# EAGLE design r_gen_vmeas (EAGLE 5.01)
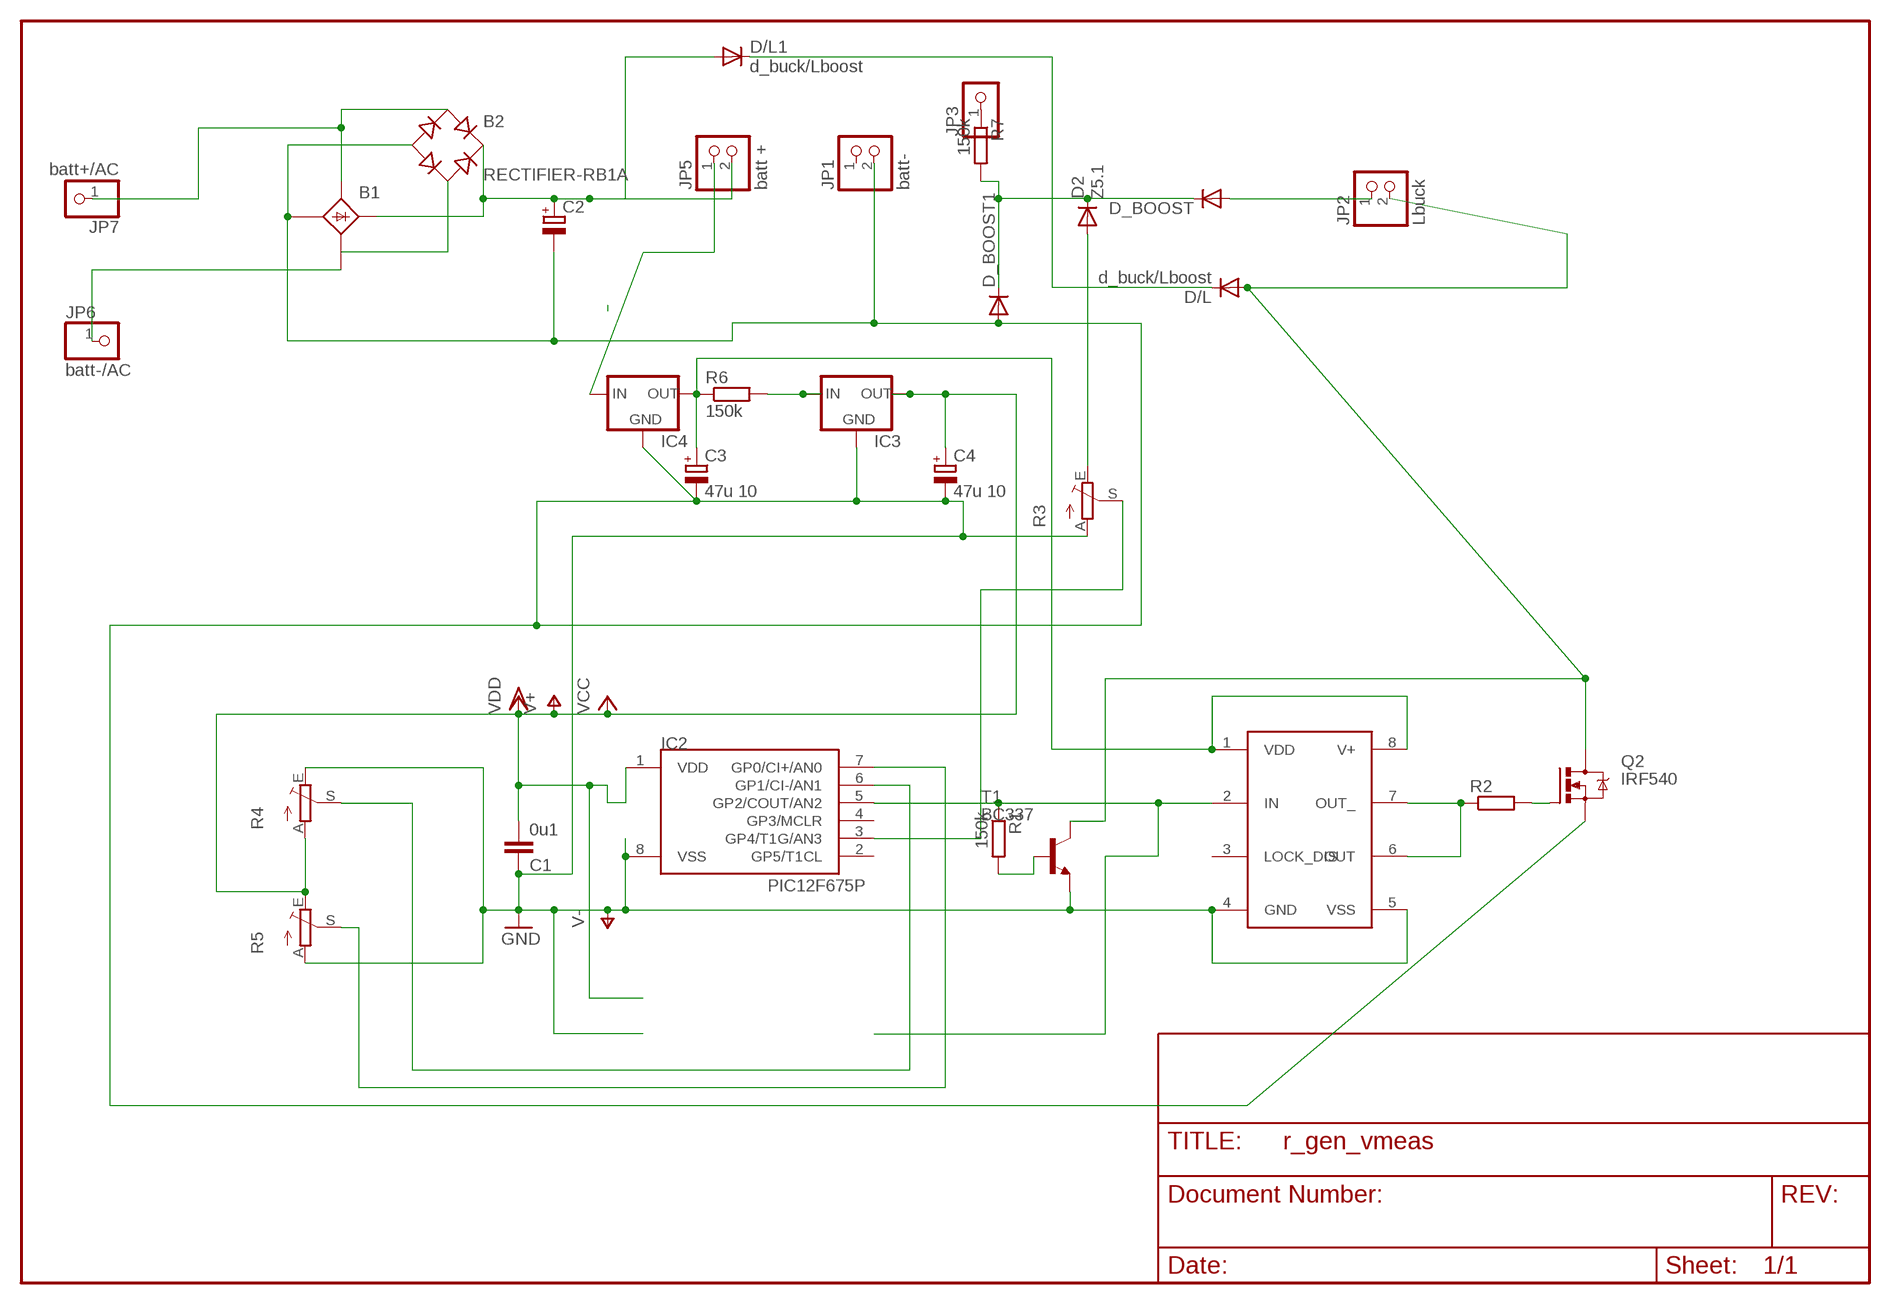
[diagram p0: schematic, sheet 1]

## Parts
B1  B25A-  [B25A-]
B2  RECTIFIER-RB1A  [RB1A]
C1  0u1  C-EU050-025X075  [C050-025X075]
C2  CPOL-EUE7.5-18  [E7,5-18]
C3  47u 10  CPOL-EUE2,5-6E  [E2,5-6E]
C4  47u 10  CPOL-EUE2.5-6  [E2,5-6]
D2  Z5.1  DIODE-D-7.5  [D-7.5]
D/L  d_buck/Lboost  DIODE-C1702-05  [C1702-05]
D/L1  d_buck/Lboost  DIODE-DO201-15  [DO201-15]
D_BOOST  DIODE-DO201-15  [DO201-15]
D_BOOST1  DIODE-DO201-15  [DO201-15]
IC1  TC4432X  [SO-08]
IC2  PIC12F675P  [DIL8]
IC3  78LXX  [78LXX]
IC4  78LXX  [78LXX]
JP1  batt-  PINHD-1X2  [1X02]
JP2  Lbuck  PINHD-1X2  [1X02]
JP3  PINHD-1X1  [1X01]
JP5  batt +  PINHD-1X2  [1X02]
JP6  batt-/AC  PINHD-1X1  [1X01]
JP7  batt+/AC  PINHD-1X1  [1X01]
Q2  IRF540  [TO220BV]
R1  150k  R-EU_0207/12  [0207/12]
R2  R-EU_R1206  [R1206]
R3  TRIM_EU-CA6V  [CA6V]
R4  TRIM_EU-CA6V  [CA6V]
R5  TRIM_EU-CA6V  [CA6V]
R6  150k  R-EU_0204/7  [0204/7]
R7  150k  R-EU_0207/12  [0207/12]
T1  BC337  [TO92]

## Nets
LOAD: D2.C D_BOOST1.C D_BOOST.C R7.2
N$1: IC4.IN JP5.1
N$2: D/L1.C D/L.C
N$3: B1.AC2-(AC2) JP6.1
N$4: C3.+ IC1.1(VDD) IC1.8(V+) IC4.OUT R6.1
N$5: D_BOOST.A JP2.1
N$6: R1.2 T1.2(B)
N$7: IC1.6(OUT) IC1.7(OUT_) R2.1
N$8: B1.AC1 B2.AC1 JP7.1
N$9: D/L.A JP2.2 Q2.D T1.3(C)
N$10: B1.+ B2.+ C2.+ D/L1.A JP5.2
N$11: B1.AC2 B2.AC2
N$12: IC2.3(GP4/T1G/AN3) R3.S
N$13: IC2.7(GP0/CI+/AN0) R5.S
N$14: IC1.2(IN) IC2.5(GP2/COUT/AN2) R1.1
N$15: IC2.6(GP1/CI-/AN1) R4.S
N$16: D2.A R3.E
N$17: Q2.G R2.2
N$19: JP3.1 R7.1
N$20: IC3.IN R6.2
V+: C1.2 C4.+ IC2.1(VDD) IC3.OUT R4.A R5.E ; supply symbol labelled VCC, VDD
V-: B1.-1(-) B2.- C1.1 C2.- C3.- C4.- D_BOOST1.A IC1.4(GND) IC1.5(VSS) IC2.8(VSS) IC3.GND IC4.GND JP1.2 Q2.S R3.A R4.E R5.A T1.1(E) ; supply symbol labelled GND
Unconnected: B1.+1(+) B1.- B1.AC1-(AC1) IC1.3(LOCK_DIS) IC2.2(GP5/T1CL) IC2.4(GP3/MCLR) JP1.1

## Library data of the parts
B1 = rectifier:B25A-: RECTIFIER 25-A bridge
B2 = rectifier:RECTIFIER-: Rectifier
C1 = rcl:C-EU: CAPACITOR, European symbol
C2-C4 = rcl:CPOL-EU: POLARIZED CAPACITOR, European symbol
D2 D/L D/L1 D_BOOST D_BOOST1 = diode:DIODE-: DIODE
IC1 = microchip:TC4432
IC2 = microchip-3:PIC12F6*: uPC nW 1k Program Flash memory 2x Timer Comparator 10b A/D converter/ 4xIN
IC3 IC4 = v-reg:78LXX: VOLTAGE REGULATOR
JP1 JP2 JP5 = pinhead:PINHD-1X2: PIN HEADER
JP3 JP6 JP7 = pinhead:PINHD-1X1: PIN HEADER
Q2 = transistor-power:IRF540: HEXFET Power MOSFET
R1 R6 R7 = rcl:R-EU_: RESISTOR, European symbol
R2 = rcl-2:R-EU_: RESISTOR, European symbol
R3-R5 = pot:TRIM_EU-: POTENTIOMETER
T1 = transistor-neu-to92:BC337: NPN TRANSISTOR

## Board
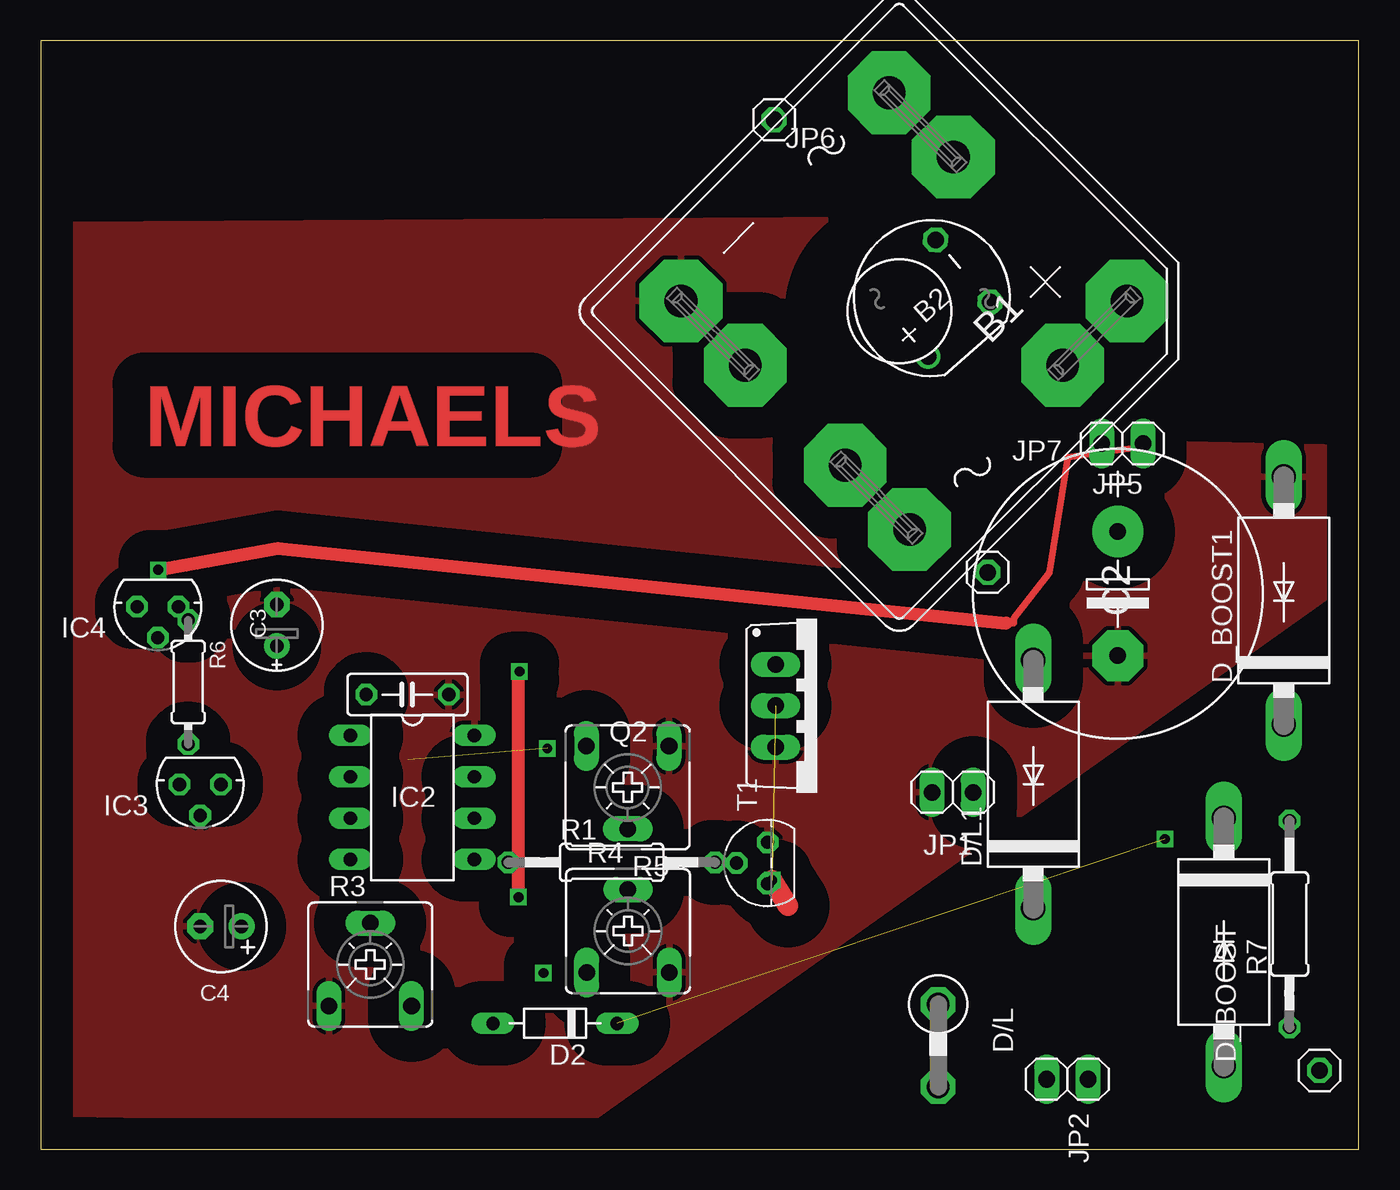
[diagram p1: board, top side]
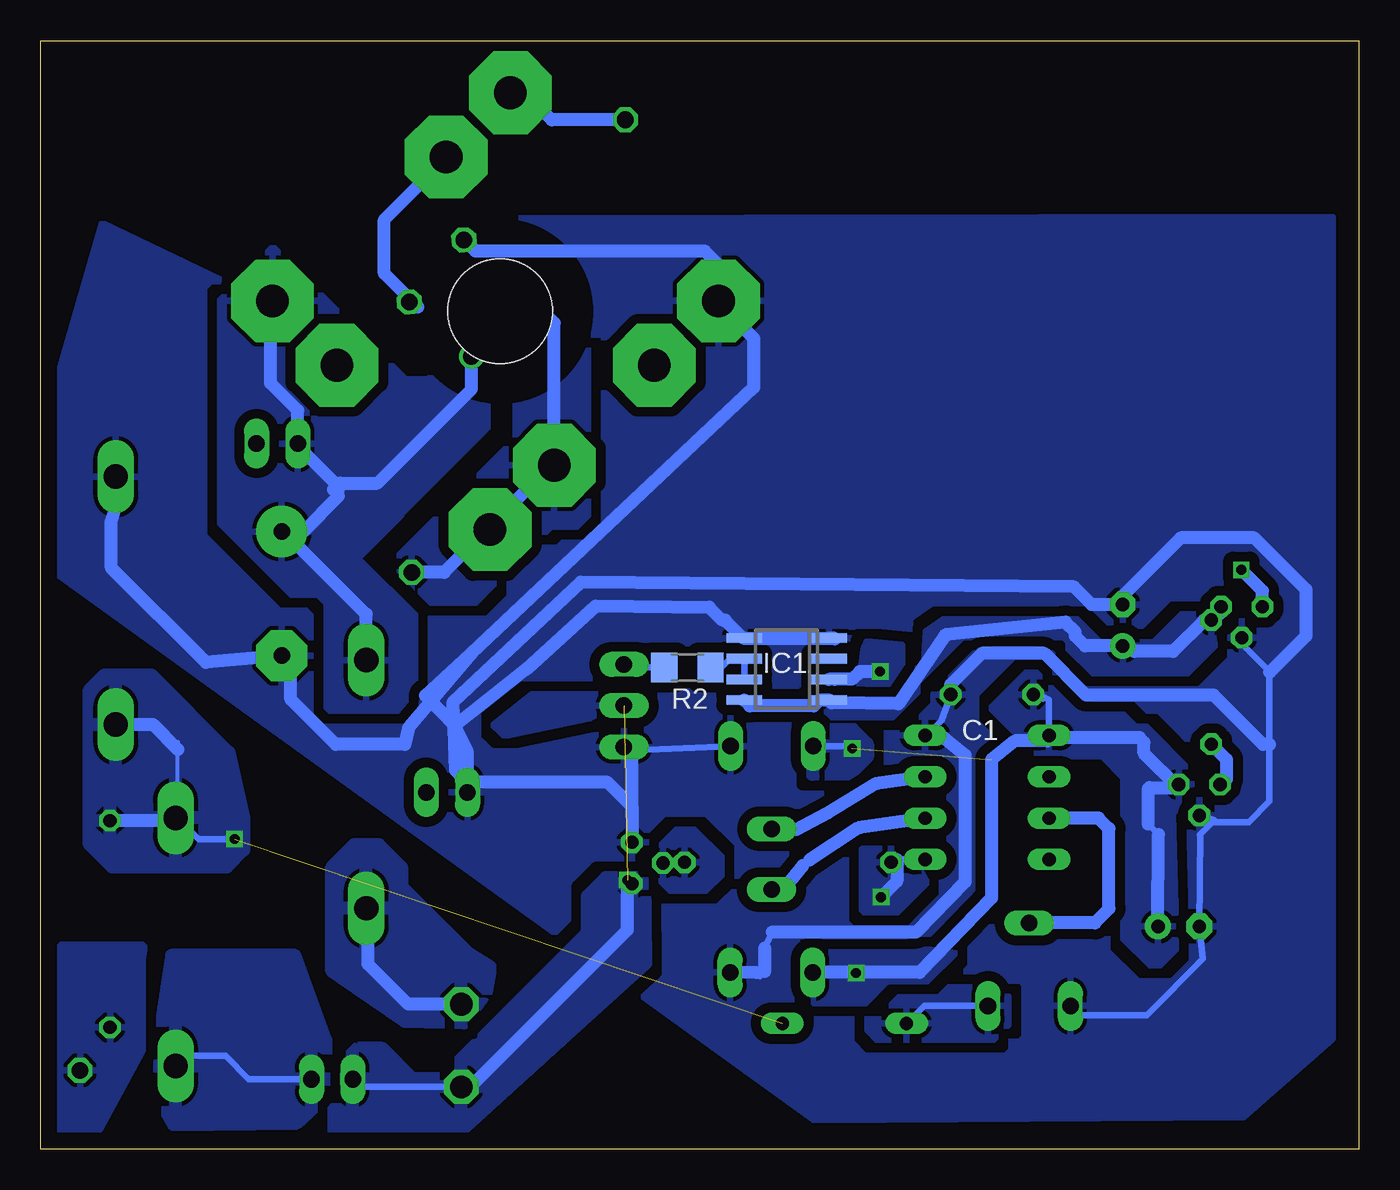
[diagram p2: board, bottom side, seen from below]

Size 81 x 68.09 mm. Coordinates in mm from the lower left corner, seen from the top.
Outline: 0,0 81,0 81,68.09 0,68.09 0,0
Copper layers (1*16): Top 0.035mm / dielectric 1.5mm / Bottom 0.035mm
Design rules "default": minimum track width 10mil, minimum drill 24mil, track to track 8mil, track to pad 8mil, pad to pad 8mil, via to via 8mil, smd to smd 8mil, copper to edge 40mil, drill to drill 8mil, minimum pad ring 10mil, minimum via ring 8mil, stop-mask expansion 4mil, vias tented up to drill 0mil, thermal gap 10mil

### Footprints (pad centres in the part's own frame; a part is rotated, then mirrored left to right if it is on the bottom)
B25A- = drill 2.007 pad 5.08 octagon: + -10.338,9.449; +1 -4.75,9.449; - 9.042,-4.343; -1 9.042,-9.931; AC1 9.042,4.343; AC1- 9.042,9.931; AC2 -9.042,-4.343; AC2- -9.042,-9.931 | hole 6.401: 0,0
RB1A = drill 1.016 round: + -2.54,2.54 | drill 1.016 octagon: - 2.54,-2.54; AC1 2.54,2.54; AC2 -2.54,-2.54
C050-025X075 = drill 0.813 octagon: 1 -2.54,0; 2 2.54,0
E7,5-18 = drill 1.016 pad 3.15 round: + -3.81,0 | drill 1.016 pad 3.15 octagon: - 3.81,0
E2,5-6E = drill 0.813 pad 1.575 round: + -1.27,0 | drill 0.813 pad 1.575 octagon: - 1.27,0
E2,5-6 = drill 0.813 pad 1.6 round: + -1.27,0 | drill 0.813 pad 1.6 octagon: - 1.27,0
D-7.5 = drill 0.813 long: A 3.81,0; C -3.81,0
C1702-05 = drill 1.397 octagon: A 2.54,0; C -2.54,0
DO201-15 = drill 1.499 long: A 7.62,0; C -7.62,0
SO-08 = smd 0.6 x 2.2: 1 -1.905,-2.6; 2 -0.635,-2.6; 3 0.635,-2.6; 4 1.905,-2.6; 5 1.905,2.6; 6 0.635,2.6; 7 -0.635,2.6; 8 -1.905,2.6
DIL8 = drill 0.813 long: 1 -3.81,-3.81; 2 -1.27,-3.81; 3 1.27,-3.81; 4 3.81,-3.81; 5 3.81,3.81; 6 1.27,3.81; 7 -1.27,3.81; 8 -3.81,3.81
78LXX = drill 0.813 octagon: GND 0,1.905; IN 1.27,0; OUT -1.27,0
1X02 = drill 1.016 long: 1 -1.27,0; 2 1.27,0
1X01 = drill 1.016 octagon: 1 0,0
TO220BV = drill 1.016 long: D 0,-2.54; G -2.54,-2.54; S 2.54,-2.54
0207/12 = drill 0.813 octagon: 1 -6.35,0; 2 6.35,0
R1206 = smd 1.6 x 1.803: 1 -1.422,0; 2 1.422,0
CA6V = drill 1.016 long: A -2.54,-2.54; E 2.54,-2.54; S 0,2.54
0204/7 = drill 0.813 octagon: 1 -3.81,0; 2 3.81,0
TO92 = drill 0.813 octagon: 1 1.27,0; 2 0,1.905; 3 -1.27,0

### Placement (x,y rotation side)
B1  52.76,51.47 225 top
B2  54.76,52.27 131.3 top
C1  22.54,27.93 180 top
C2  66.19,34.12 270 top
C3  14.51,32.18 90 top
C4  11.07,13.68 180 top
D2  31.61,7.72 180 top
D/L  55.15,6.36 270 top
D/L1  60.99,22.42 90 top
D_BOOST  72.7,12.73 270 top
D_BOOST1  76.39,33.69 90 top
IC1  35.16,29.49 90 bottom
IC2  22.84,21.6 270 top
IC3  9.8,22.4 180 top
IC4  7.2,33.32 180 top
JP1  56.04,21.92 180 top
JP2  63.09,4.29 180 top
JP3  78.58,4.84 0 top
JP5  66.47,43.35 180 top
JP6  45.07,63.23 0 top
JP7  58.2,35.43 0 top
Q2  47.7,27.24 270 top
R1  35.09,17.61 0 top
R2  41.26,29.59 180 bottom
R3  20.25,11.34 0 top
R4  36.09,13.4 0 top
R5  36.07,22.22 180 top
R6  9.06,28.69 270 top
R7  76.74,13.83 90 top
T1  44.66,17.58 90 top

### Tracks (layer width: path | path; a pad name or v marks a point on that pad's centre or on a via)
LOAD  (via drill 0.6)  (1 unrouted)
  Bottom 0.254: 72.58,25.02 72.58,24.55 72.58,22.48 D_BOOST.C
  Bottom 0.406: 72.7,20.46 72.83,20.59 | 72.7,20.46 D_BOOST.C | v69.08,19.05 71.29,19.05 72.7,20.46
  Bottom 0.813: D_BOOST1.C 74.1,26.07 72.58,24.55 | D_BOOST.C 72.6,20.34 72.58,20.32 72.72,20.18 R7.2
  pour Bottom (isolate 0.61): 68.51,20.29 68.51,18.38 69.57,17.32 76.62,17.32 78.01,18.72 78.01,28.21 77.09,29.13 74.19,29.13 69.44,24.38
N$1  (via drill 0.6)
  Top 0.406: 59.33,32.31 59.81,32.31 59.81,32.6 61.98,35.42 63.13,42.49 67.92,43.18 JP5.1
  Top 0.813: v7.22,35.59 14.56,36.91 59.33,32.31
  Bottom 0.813: IC4.IN 5.93,34.29 v7.22,35.59
N$2
  Bottom 0.813: D/L.C 58.42,8.9 60.88,11.37 60.88,14.57 60.99,14.68 D/L1.C
  pour Bottom (isolate 0.61): 53.36,11.19 53.63,9.65 55,7.75 58.62,7.84 63.12,10.93 63.12,17.34 61.73,18.72 60.22,18.72 58.82,17.32 58.82,16.14 54.73,12.05
N$3
  Bottom 0.813: JP6.1 49.6,63.23 51.95,65.58 51.95,64.49 51.67,64.21 51.69,64.21 52.13,64.66 B1.AC2-
N$4
  Bottom 0.813: IC1.8 37.76,27.57 37.42,27.23 33.49,27.23 33.13,27.58 IC1.1 32.39,27.42 28.3,27.36 25.41,31.59 18.02,32.37 17.42,31.77 17.42,31.51 16.82,30.91 C3.+ 14.13,30.91 13.8,30.58 11.43,30.58 9.51,32.5 R6.1 8.99,32.44 8.47,32.96 IC4.OUT
  pour Bottom (isolate 0.61, rank 2): 9.15,32.87 10.89,32.87 12.63,31.13 15.88,31.13 17.31,32.55 25.5,32.59 26.62,31.81 26.72,29.86 29.44,27.9 33.61,27.95 33.61,26.85 33.3,26.53 28.64,26.53 27.12,28.04 27.12,28.66 24.34,31.45 18.17,31.45 17.85,31.13 17.85,30.72 16.35,29.22 10.5,29.22 8.84,30.89
N$5
  Bottom 0.406: JP2.1 68.21,4.29 69.64,5.73 72.04,5.73 72.67,5.11 D_BOOST.A
  pour Bottom (isolate 0.61): 63.45,4.8 63.45,6.65 65.38,11.9 72.96,11.9 73.66,7.3 73.76,3.07 72.84,1.51 65.27,1.6 63.7,3.02
N$6
  pour Bottom (isolate 0.61): 43.14,17.65 43.14,18.44 41.94,19.63 40.83,19.63 39.18,17.98 39.18,16.8 40.1,15.88 42.34,15.88 42.94,16.47
N$7
  Bottom 0.406: 37.92,28.85 37.97,28.8 | 37.92,28.85 IC1.7 | 37.92,28.85 37.76,29.01 IC1.6 38.66,30.12 39.51,29.27 39.82,29.59 R2.1
N$8
  Bottom 0.813: JP7.1 56.21,35.43 49.49,42.15 49.44,42.1 B1.AC1 49.44,50.74 51.21,52.51 | 51.21,52.51 51.41,52.7 | 51.21,52.51 B2.AC1
  pour Bottom (isolate 0.61, rank 2): 48.6,50.61 47.82,50.61 47.35,50.14 47.35,38.91 48.03,38.24 49.63,38.24 54.29,33.58 57.05,33.58 58.95,35.48 58.95,36.54 51.83,43.66 51.83,48.9 50.11,50.61
N$9  (via drill 0.6)  (1 unrouted)
  Top 1.27: v44.94,16.52 45.91,14.96
  Bottom 0.406: 61.98,4.29 61.98,4.46 | 61.98,4.29 JP2.2 | D/L.A 61.98,3.82 61.98,4.29
  Bottom 0.813: D/L.A 54.58,3.82 44.94,13.46 v44.94,16.52 44.73,16.31 T1.3
  pour Bottom (isolate 0.813): 46.03,27.95 52.13,27.95 53.46,26.62 53.46,26.28 52.54,25.35 47.24,26.48 46.39,26.9
  pour Bottom (isolate 0.61, rank 2): 43.86,16.68 46.29,16.68 47.42,15.54 47.42,13.3 56.38,4.33 58.16,4.33 60.02,6.18 61.53,6.18 62.39,5.32 65.74,0.47 65.21,-0.06 56.51,-0.06 43.8,11.46
N$10
  Bottom 0.813: D/L1.A 60.99,32.87 66.06,37.94 C2.+ 64.88,37.94 62.71,40.11 62.71,40.51 | 62.71,40.51 62.71,40.73 65.2,43.22 JP5.2 65.2,45.38 66.88,47.05 66.88,51.87 67.08,52.07 67.05,52.1 B1.+ | B2.+ 54.53,46.69 60.3,40.92 62.62,40.92 63.03,40.51 62.71,40.51
  pour Bottom (isolate 0.61, rank 2): 53.54,49 53.54,44.32 58.86,39 58.86,38.9 61.71,36.06 61.24,36.06 58,32.82 58,27.88 58.95,26.92 63.33,26.92 63.42,27.01 63.42,33.5 63.98,34.06 65.6,34.06 69.97,38.43 69.97,52.18 66.8,55.36 66.66,55.36 58.58,47.28 57.22,47.28 55.85,48.65 55.85,48.78 55.85,49.06 55.44,49.47
N$11
  Bottom 0.813: B1.AC2 56.08,60.89 59.89,57.09 59.89,53.8 57.83,51.74 58.38,51.74 58.52,51.88 58.36,52.04 B2.AC2
N$12
  Bottom 0.406: 20.63,13.91 20.61,13.88 R3.S
  Bottom 0.813: IC2.3 16,20.33 15.35,19.68 15.35,14.77 16.21,13.91 20.63,13.91
N$13
  Bottom 0.406: 36.34,19.41 R5.S
  Bottom 0.813: IC2.7 29.71,22.44 32.62,20.66 34.58,19.62 R5.S
N$14  (via drill 0.6)
  Top 0.813: v29.36,15.48 29.36,29.27 v29.42,29.34
  Bottom 0.406: 28.88,17.31 29,17.18 | R1.1 28.88,17.31 | IC2.5 28.39,17.79 28.88,17.31
  Bottom 0.813: 28.39,17.79 28.39,16.45 v29.36,15.48 | v29.42,29.34 30.67,29.34 31.14,28.87 32.19,28.87 32.2,28.85 IC1.2
  pour Bottom (isolate 0.61, rank 2): 27.72,18.44 30.45,18.44 30.53,18.52 30.53,14.67 30.04,14.19 28.69,14.19 26.51,16.36
  pour Bottom (isolate 0.61): 30.48,28.26 28.91,27.94 28.06,29.07 28.06,30.98 30.24,31.2 30.44,30.68 30.72,28.51 30.91,28.32
N$15
  Bottom 0.406: 35.65,15.84 35.28,16.09 R4.S | 33.73,17.77 34.17,17.44
  Bottom 0.813: IC2.6 30.74,19.74 33.73,17.77 | 34.17,17.44 35.28,16.09
N$16
  Bottom 0.406: D2.A 27.77,7.72 26.69,8.8 R3.E
  pour Bottom (isolate 0.61, rank 2): 23.15,9.94 28.36,9.94 30.21,8.09 30.21,7.3 29.64,6.73 22.42,6.73 21.55,7.61 21.55,9.39 21.87,9.7
N$17
  Bottom 0.406: Q2.G 45.09,29.78 44.9,29.59 R2.2
N$19
  pour Bottom (isolate 0.61): 74.74,11.63 74.74,6.03 77.35,1.22 81.01,1.22 81.24,3.64 81.24,11.06 79.75,12.55 74.74,12.55 74.62,12.43
N$20
  Bottom 0.813: R6.2 9.06,24.87 8.12,23.93 8.12,22.75 8.53,22.34 IC3.IN
V+  (via drill 0.6)  (1 unrouted)
  Top 0.406: v30.9,10.82 31.14,11.06
  Bottom 0.406: 19.11,25.08 18.92,25.27 19.03,25.39 IC2.1 19.03,27.61 20.07,28.17 | 20.07,28.17 19.43,27.67 | 20.07,28.17 C1.2 | 12.94,22.19 12.94,22.12 12.86,22.2 | 12.32,19.34 12.94,19.96 | R5.E 31.28,24.76 v31.14,24.61 | R4.A 31.95,10.76 31.94,10.74 31.86,10.82 v30.9,10.82 | 11.07,22.2 IC3.OUT
  Bottom 0.813: R4.A 26.97,10.86 22.58,15.42 22.58,23.93 21.13,25.08 19.11,25.08 | C4.+ 12.32,19.34 | 12.94,19.96 12.94,22.12 | 18.92,25.27 13.48,25.27 13.21,24.99 13.21,24.33 11.07,22.2 12.86,22.2
  pour Bottom (isolate 0.61, rank 2): 33.59,25.81 31.09,25.81 30.2,24.92 30.2,24.08 31.25,23.03 33.59,23.03 33.98,23.42
  pour Bottom (isolate 0.61, rank 2): 11.24,13.77 11.24,12.24 12.19,11.29 12.85,11.29 14.46,12.9 14.46,22.8 15.8,24.13 19.68,24.13 22.64,27.09 22.63,27.09 19.97,29.74 17.51,29.74 13.71,25.95 13.04,25.95 10.28,23.19 10.28,21.76 11.43,20.61
  pour Bottom (isolate 0.61): 27.14,12.36 33.94,12.36 33.94,12.12 33.47,12.12 33.47,8.95 30.3,8.95 28.95,10.3 26.5,10.3 24.76,12.04
V-
  Bottom 0.406: 9.74,19.34 9.78,19.3 | 9.74,19.34 C4.- 9.57,11.7 13.04,8.23 17.18,8.23 17.71,8.76 R3.A 17.71,8.36 | 9.74,19.34 8.87,20.21 IC3.GND 9.8,20.62 | Q2.S 45.18,24.7 45.28,24.6 45.16,24.48 R5.A | 25.69,25.41 IC2.8 26.55,25.41 25.65,26.31 C1.1 | 36.04,13.34 36.52,12.37 | 37.03,10.85 36.81,10.63 36.52,10.92 | 36.9,11.02 37.03,10.9 R4.E | IC4.GND 7.2,31.05 5.5,29.35 5.5,29.31 5.5,24.87 5.5,21.36 6.77,20.09 10.12,20.09 10.12,20.31 9.8,20.62 | 9.8,20.62 9.76,20.66
  Bottom 0.813: 25.69,25.41 24.2,24.22 24.2,16.4 27.19,13.34 36.04,13.34 | 37.03,10.85 R4.E | 36.52,12.37 36.52,10.92 | 54.77,22.57 JP1.2 54.77,21.7 | 55.57,26.02 54.77,24.38 54.77,21.7 | 55.57,26.02 57.35,27.86 54.54,30.42 | 54.54,30.42 37.18,46.79 37.18,49.81 39.34,51.97 B1.-1 39.34,54.32 40.19,55.17 54.28,55.17 54.99,55.88 | 54.77,22.57 54.81,22.57 55.52,23.28 55.69,27.45 47.81,34.84 17.5,34.54 16.41,33.45 C3.- 14.51,33.98 10.94,37.55 6.42,37.55 3.23,34.37 3.23,31.52 5.45,29.31 5.5,29.31 | 55.57,26.02 51.23,29.44 51.11,29.52 46.88,33.38 39.92,33.3 39.12,32.5 38.95,32.5 37.84,31.39 IC1.5 32.27,31.39 | 54.54,30.42 58.38,25.91 58.63,24.87 62.87,24.87 65.63,27.62 65.63,29.65 66.29,30.32 | 66.29,30.32 66.34,30.37 | 66.29,30.32 C2.- 70.84,29.9 76.65,35.71 76.67,38.53 75.99,40.62 76.93,40.77 D_BOOST1.A | 32.27,31.39 IC1.4 | 32.27,31.39 32.22,31.34 | C1.1 25.08,28.55 23.17,30.45 19.33,30.45 16.76,27.89 8.91,27.89 5.89,24.87 5.5,24.87 | Q2.S 45.25,24.62 44.66,24.04 44.66,21.06 | 44.66,21.06 T1.1 | 44.66,21.06 44.7,21.06 46.21,22.57 54.77,22.57 | 54.99,55.88 55.1,55.99 | 54.99,55.88 B2.- | 54.77,21.7 54.9,21.58
  pour Bottom (isolate 0.61, rank 3): 1.6,57.29 1.6,6.79 7.11,1.97 33.44,1.78 80.77,35.9 80.77,44.59 77.23,56.9 48.45,43.12 55.83,57.18
  pour Top (isolate 1.93): 1.46,56.78 55.48,57.12 49.34,44.32 61.64,36.68 70.3,43.29 81.71,43.07 80.79,35.19 33.49,1.6 1.79,2.17

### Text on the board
Top: MICHAELS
